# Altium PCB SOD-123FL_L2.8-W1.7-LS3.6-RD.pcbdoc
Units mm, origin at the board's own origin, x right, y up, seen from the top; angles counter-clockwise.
Board outline 16.8 x 14.6 mm, 2 copper layers (Top Layer, Bottom Layer), stack 0.07 mm thick; 1 components, 0 nets, 2 pads, 0 vias.
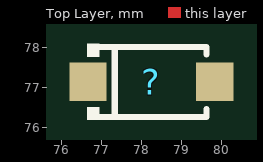
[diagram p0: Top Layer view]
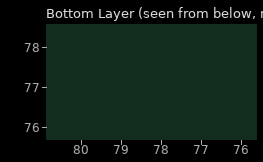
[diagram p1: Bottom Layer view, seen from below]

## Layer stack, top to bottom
Top Solder Mask Layer: solder mask 0.01, Dk 3.3
Top Layer: signal copper 0.035
Bottom Layer: signal copper 0.035
Bottom Solder Mask Layer: solder mask 0.01, Dk 3.3

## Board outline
86.65,69.85 69.85,69.85 69.85,84.455 86.65,84.455

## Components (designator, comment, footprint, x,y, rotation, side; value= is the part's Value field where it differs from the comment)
? "SOD-123FL_L2.8-W1.7-LS3.6-RD" SOD-123FL_L2.8-W1.7-LS3.6-RD 78.25,77.152 r0 top

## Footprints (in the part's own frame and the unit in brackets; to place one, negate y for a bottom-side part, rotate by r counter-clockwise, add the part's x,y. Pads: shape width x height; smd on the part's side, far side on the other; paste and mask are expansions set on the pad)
SOD-123FL_L2.8-W1.7-LS3.6-RD [mm]
  rect 0.93x0.96 smd paste+0 mask+0.051: 1(-1.585,0) 2(1.585,0)
  silkscreen extent -1.6,-0.95 1.38,0.95

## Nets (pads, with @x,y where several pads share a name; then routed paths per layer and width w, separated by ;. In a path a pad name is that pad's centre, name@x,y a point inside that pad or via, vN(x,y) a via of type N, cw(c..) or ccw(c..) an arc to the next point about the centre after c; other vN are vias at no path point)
pads on no net: ?.1 ?.2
